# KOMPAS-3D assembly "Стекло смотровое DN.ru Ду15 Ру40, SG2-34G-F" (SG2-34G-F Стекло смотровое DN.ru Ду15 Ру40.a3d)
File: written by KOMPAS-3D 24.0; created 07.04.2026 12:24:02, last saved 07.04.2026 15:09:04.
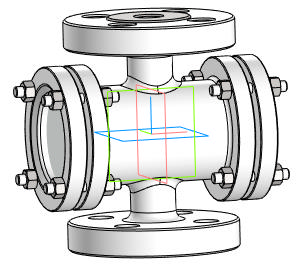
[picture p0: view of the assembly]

Document properties: Автор: Main; Полное имя файла: D:\DN.ru Аутсерс\Стекло смотровое DN.ru\Исходники\Стекло смотровое DN.ru SG2-34G-F тип В ГОСТ 21836-2021 Ду15 Ру40, углеродистая сталь, фланцевое\SG2-34G-F Стекло смотровое DN.ru Ду15 Ру40.a3d

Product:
- Component [detail]: Деталь  | qty 1  | pos. 1  | Масса: 2.979461; Автор: Main; additional columns: Типовые; source file: ДетальДеталь.m3d
- Component [detail]: Стекло  | qty 2  | pos. 2  | Масса: 0.08342; Автор: Main; source file: СтеклоСтекло.m3d
- Component [detail]: ANSI B18.2.4.2M - M6x1 - 10  | designation ANSI B18.2.4.2M - M6x1  | qty 16  | pos. 3  | Масса: 0.003008; Комментарий: Типы метрических   шестигранных гаек   2; Автор: Main; additional columns: Сталь, мягкая; source file: ANSI B18.2.4.2M - M6x1ANSI B18.2.4.2M - M6x1 - 10.m3d
- Part/product: Стекло смотровое DN.ru Ду15 Ру40  | designation SG2-34G-F
    Масса: 4
    Раздел спецификации: Прочие изделия
    Примечание: D500-00079

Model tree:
1. Массив по концентрической сетке:1  (labels: Грань.Твердое тело1; Ребро.Solid1; Ребро.Твердое тело1; Грань.Solid1)  (4 pattern instances)
     Шаг 2 = 360

Expressions: SG2-34G-F
Referenced files in D:\DN.ru Аутсерс\Стекло смотровое DN.ru\Исходники\Стекло смотровое DN.ru SG2-34G-F тип В ГОСТ 21836-2021 Ду15 Ру40, углеродистая сталь, фланцевое\: ДетальДеталь.m3d, СтеклоСтекло.m3d, ANSI B18.2.4.2M - M6x1ANSI B18.2.4.2M - M6x1 - 10.m3d
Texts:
  Стекло Стекло (1)
  Стекло Стекло (2)
  ANSI B18.2.4.2M - M6x1 ANSI B18.2.4.2M - M6x1 - 10 (1)
  ANSI B18.2.4.2M - M6x1 ANSI B18.2.4.2M - M6x1 - 10 (2)
  ANSI B18.2.4.2M - M6x1 ANSI B18.2.4.2M - M6x1 - 10 (3)
  ANSI B18.2.4.2M - M6x1 ANSI B18.2.4.2M - M6x1 - 10 (4)
  ANSI B18.2.4.2M - M6x1 ANSI B18.2.4.2M - M6x1 - 10 (5)
  ANSI B18.2.4.2M - M6x1 ANSI B18.2.4.2M - M6x1 - 10 (6)
  ANSI B18.2.4.2M - M6x1 ANSI B18.2.4.2M - M6x1 - 10 (7)
  ANSI B18.2.4.2M - M6x1 ANSI B18.2.4.2M - M6x1 - 10 (8)
  ANSI B18.2.4.2M - M6x1 ANSI B18.2.4.2M - M6x1 - 10 (9)
  ANSI B18.2.4.2M - M6x1 ANSI B18.2.4.2M - M6x1 - 10 (10)
  ANSI B18.2.4.2M - M6x1 ANSI B18.2.4.2M - M6x1 - 10 (11)
  ANSI B18.2.4.2M - M6x1 ANSI B18.2.4.2M - M6x1 - 10 (12)
  ANSI B18.2.4.2M - M6x1 ANSI B18.2.4.2M - M6x1 - 10 (13)
  ANSI B18.2.4.2M - M6x1 ANSI B18.2.4.2M - M6x1 - 10 (14)
  ANSI B18.2.4.2M - M6x1 ANSI B18.2.4.2M - M6x1 - 10 (15)
  ANSI B18.2.4.2M - M6x1 ANSI B18.2.4.2M - M6x1 - 10 (16)
  Ось Z.Начало координат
